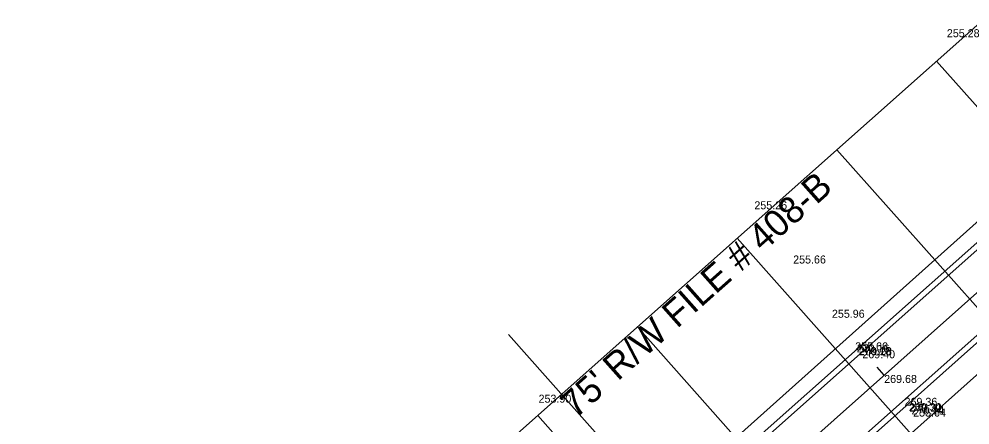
# Model space of a CAD drawing. Extents: x 49683 to 58852, y 49525 to 54803.
# Drawn here: x 53192.2 to 53548.7, y 51528.4 to 51680.6 of the extents above; entities that cross this region are included whole.
import ezdxf

# ---------------------------------------------------------------- set-up
doc = ezdxf.new("R2010")
doc.units = 0
for name, color, linetype in [('Level 1', 7, 'Continuous'), ('Level 11', 7, 'Continuous'), ('Level 13', 7, 'Continuous'), ('Level 15', 7, 'Continuous'), ('Level 25', 7, 'Continuous'), ('Level 3', 7, 'Continuous'), ('Level 32', 7, 'Continuous'), ('Level 5', 7, 'Continuous'), ('Level 50', 7, 'Continuous')]:
    doc.layers.add(name, color=color, linetype=linetype)

msp = doc.modelspace()

# ---------------------------------------------------------------- linework, layer by layer
at = {"layer": 'Level 1'}
for p, q in [((52544.81, 50683.3), (55534.58, 53340.86)), ((53516.57, 51547.09), (53513.91, 51550.08))]:
    msp.add_line(p, q, dxfattribs=at)
at = {"layer": 'Level 11'}
msp.add_line((53424.49, 51490.93), (53894.91, 51911.93), dxfattribs=at)
at = {"layer": 'Level 13'}
msp.add_line((53573.51, 51698.05), (53335.95, 51486.88), dxfattribs=at)
at = {"layer": 'Level 15'}
msp.add_line((53460.73, 51466.68), (53909.18, 51865.3), dxfattribs=at)
at = {"layer": 'Level 3'}
for p, q in [((53434.09, 51489.84), (53883.27, 51889.18)), ((53449.72, 51471.81), (53898.74, 51870.57))]:
    msp.add_line(p, q, dxfattribs=at)
at = {"layer": 'Level 5'}
for p, q in [((53432.56, 51491.2), (53881.99, 51890.68)), ((53900.07, 51869.4), (53451.19, 51470.16))]:
    msp.add_line(p, q, dxfattribs=at)
at = {"layer": 'Level 50'}
for p, q in [((53536.14, 51664.83), (53695.59, 51485.45)), ((53498.77, 51631.61), (53658.22, 51452.23)), ((53461.4, 51598.39), (53620.85, 51419.01)), ((53424.03, 51565.17), (53583.47, 51385.79)), ((53375.7, 51562.35), (53575, 51338.12)), ((53386.66, 51531.95), (53546.1, 51352.57))]:
    msp.add_line(p, q, dxfattribs=at)

# ---------------------------------------------------------------- texts
at = {"layer": 'Level 25'}
msp.add_text("75' R/W FILE # 408-B", height=10, rotation=41.6333, dxfattribs=at).set_placement((53400.89, 51530.55))
at = {"layer": 'Level 32'}
for s, p in [('255.28', (53540.05, 51673.78)), ('255.26', (53467.89, 51609.25)), ('255.66', (53482.43, 51588.92)), ('255.96', (53496.96, 51568.58)), ('255.66', (53505.68, 51556.37)), ('270.16', (53506.27, 51555.56)), ('270.18', (53506.93, 51554.62)), ('269.28', (53507.19, 51554.47)), ('269.40', (53508.36, 51553.38)), ('269.68', (53516.55, 51544.13)), ('253.90', (53386.98, 51536.72)), ('269.36', (53524.19, 51535.56)), ('269.30', (53525.79, 51533.55)), ('270.21', (53526.04, 51533.34)), ('270.14', (53526.81, 51532.33)), ('255.64', (53527.42, 51531.53))]:
    msp.add_text(s, height=3, dxfattribs=at).set_placement(p)

doc.saveas('drawing.dxf')
